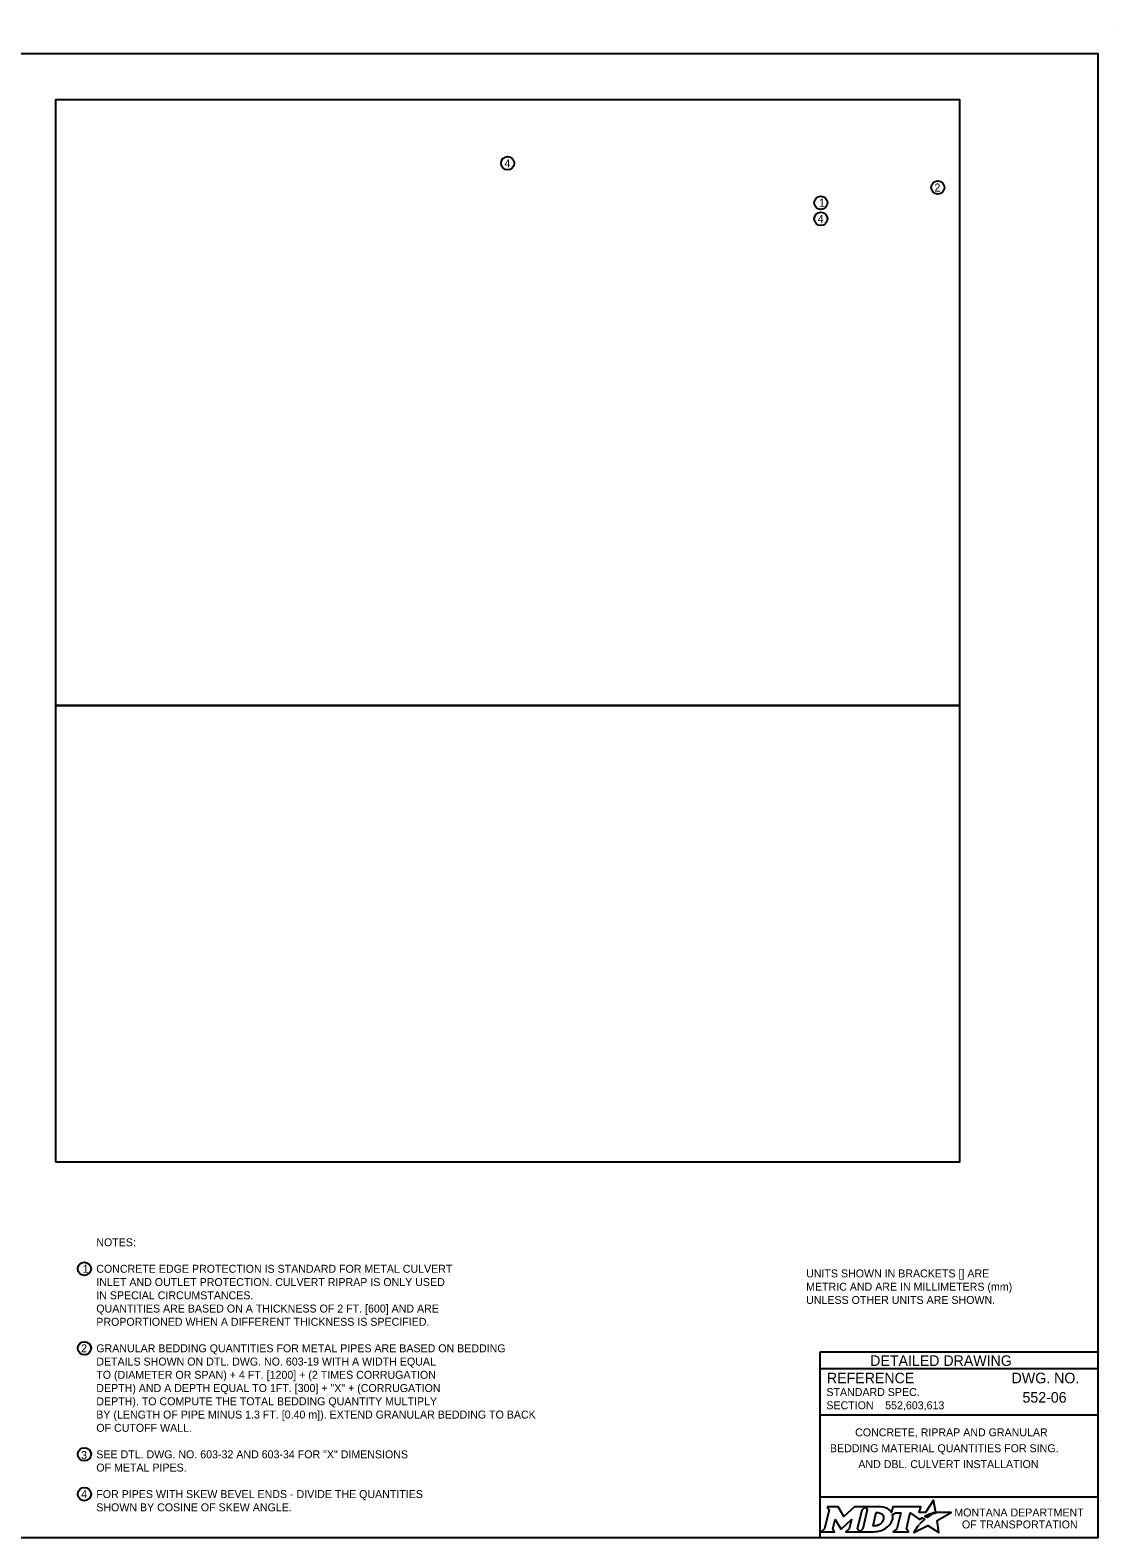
# Model space of a CAD drawing. Extents: x 49991.4 to 50047.6, y 49987.6 to 50011.4.
# Drawn here: x 50008.69 to 50016.9, y 49987.8 to 49999.18 of the extents above; entities that cross this region are included whole.
import ezdxf

# ---------------------------------------------------------------- set-up
doc = ezdxf.new("R2010")
doc.units = 0
for name, color, linetype in [('Default', 7, 'Continuous'), ('Level 1', 7, 'Continuous'), ('Level 2', 7, 'Continuous'), ('Level 5', 7, 'Continuous')]:
    doc.layers.add(name, color=color, linetype=linetype)

msp = doc.modelspace()

# ---------------------------------------------------------------- linework, layer by layer
at = {"layer": 'Default'}
for points in [[(50008.881, 49994.079), (50015.707, 49994.079), (50015.707, 49998.649), (50008.881, 49998.649)], [(50008.881, 49990.635), (50015.707, 49990.635), (50015.707, 49994.079), (50008.881, 49994.079)]]:
    msp.add_lwpolyline(points, close=True, dxfattribs=at)
for points in [[(50015.513, 49987.981), (50015.502, 49987.987), (50015.514, 49987.99), (50015.526, 49987.991), (50015.508, 49988.082), (50015.449, 49987.99), (50015.401, 49987.99), (50015.412, 49988.034), (50015.202, 49988.034), (50015.192, 49987.991), (50015.186, 49988)], [(50014.706, 49988.034), (50014.72, 49988.01), (50014.686, 49987.867), (50014.66, 49987.845), (50014.762, 49987.845), (50014.749, 49987.867), (50014.765, 49987.937), (50014.809, 49987.868), (50014.814, 49987.868), (50014.889, 49987.938), (50014.872, 49987.867), (50014.848, 49987.845), (50014.949, 49987.845), (50014.936, 49987.868), (50014.969, 49988.011)], [(50014.969, 49988.011), (50014.994, 49988.034), (50014.912, 49988.034), (50014.832, 49987.961), (50014.788, 49988.034), (50014.706, 49988.034)], [(50015.108, 49988.034), (50014.994, 49988.034), (50015.009, 49988.011), (50014.975, 49987.867), (50014.949, 49987.845), (50015.06, 49987.845)], [(50015.132, 49987.947), (50015.13, 49987.939), (50015.127, 49987.93), (50015.123, 49987.922), (50015.118, 49987.914), (50015.111, 49987.907), (50015.103, 49987.901), (50015.095, 49987.896), (50015.086, 49987.892), (50015.077, 49987.89), (50015.067, 49987.889), (50015.052, 49987.889), (50015.075, 49987.989), (50015.091, 49987.989), (50015.099, 49987.988), (50015.106, 49987.986), (50015.113, 49987.983), (50015.119, 49987.979), (50015.124, 49987.974), (50015.128, 49987.968), (50015.13, 49987.962), (50015.132, 49987.955), (50015.132, 49987.952), (50015.132, 49987.947)], [(50015.199, 49987.975), (50015.224, 49987.988), (50015.261, 49987.988), (50015.232, 49987.867), (50015.205, 49987.845), (50015.321, 49987.845), (50015.304, 49987.867), (50015.332, 49987.988), (50015.403, 49987.936), (50015.424, 49987.951), (50015.444, 49987.94)], [(50015.388, 49987.884), (50015.373, 49987.86), (50015.368, 49987.852), (50015.362, 49987.844), (50015.36, 49987.839), (50015.465, 49987.893), (50015.549, 49987.838), (50015.536, 49987.93), (50015.643, 49987.989), (50015.594, 49987.989), (50015.564, 49987.99), (50015.543, 49987.99), (50015.536, 49987.989), (50015.531, 49987.987), (50015.523, 49987.985), (50015.513, 49987.981)], [(50015.462, 49987.954), (50015.46, 49987.952), (50015.442, 49987.961), (50015.452, 49987.967), (50015.456, 49987.969), (50015.465, 49987.973), (50015.47, 49987.976), (50015.478, 49987.979), (50015.485, 49987.982), (50015.497, 49987.974), (50015.493, 49987.972), (50015.489, 49987.97), (50015.484, 49987.967), (50015.479, 49987.965), (50015.478, 49987.963), (50015.475, 49987.962), (50015.472, 49987.96), (50015.47, 49987.959), (50015.467, 49987.957), (50015.465, 49987.955), (50015.462, 49987.954)], [(50015.106, 49987.852), (50015.114, 49987.855), (50015.127, 49987.86), (50015.148, 49987.871)], [(50015.402, 49987.9), (50015.402, 49987.9)]]:
    msp.add_lwpolyline(points, dxfattribs=at)
for centre in [(50012.294, 49998.171), (50014.658, 49997.751), (50009.099, 49988.129)]:
    msp.add_circle(centre, 0.05, dxfattribs=at)
for centre, radius, start, end in [((50015.087, 49987.973), 0.118, 300.9103, 339.1383), ((50015.131, 49987.955), 0.0709, 339.5329, 15.8582)]:
    msp.add_arc(centre, radius, start, end, dxfattribs=at)
for centre, major_axis, ratio, start_param, end_param in [((50015.106, 49987.986), (0.0834, -0.0037), 0.568097, 0.61298, 1.570796), ((50015.161, 49987.994), (0.0361, -0.0295), 0.469099, 1.225588, 1.570796), ((50015.433, 49987.93), (-0.0112, -0.0097), 0.021651, 3.157348, 6.283185), ((50015.06, 49987.993), (0, 0.148), 0.987302, 3.139398, 3.456847), ((50015.395, 49987.892), (-0.00694, -0.00806), 0.008222, 0, 3.137361), ((50015.412, 49987.911), (-0.0098, -0.0102), 0.016458, 3.141593, 6.279097)]:
    msp.add_ellipse(centre, major_axis=major_axis, ratio=ratio, start_param=start_param, end_param=end_param, dxfattribs=at)
at = {"layer": 'Level 1'}
msp.add_line((50016.9, 49999.176), (50016.9, 49999.176), dxfattribs=at)
msp.add_lwpolyline([(49999.384, 49998.999), (50016.75, 49998.999), (50016.75, 49987.799), (49999.384, 49987.799)], close=True, dxfattribs=at)
at = {"layer": 'Level 2'}
for centre in [(50015.541, 49997.988), (50014.658, 49997.873), (50009.099, 49989.829), (50009.099, 49989.229), (50009.099, 49988.429)]:
    msp.add_circle(centre, 0.05, dxfattribs=at)
at = {"layer": 'Level 5'}
for p, q in [((50016.75, 49989.199), (50014.65, 49989.199)), ((50014.65, 49989.199), (50014.65, 49987.799)), ((50016.75, 49989.074), (50014.65, 49989.074)), ((50016.386, 49988.859), (50016.386, 49988.859)), ((50016.75, 49988.724), (50014.65, 49988.724)), ((50015.144, 49988.799), (50015.144, 49988.799)), ((50015.7, 49988.475), (50015.7, 49988.475)), ((50016.75, 49988.106), (50014.65, 49988.106))]:
    msp.add_line(p, q, dxfattribs=at)

# ---------------------------------------------------------------- texts
at = {"layer": 'Default'}
for s, p in [('4', (50012.27, 49998.141)), ('4', (50014.634, 49997.721)), ('4', (50009.075, 49988.099)), ('MONTANA DEPARTMENT', (50015.666, 49987.96)), ('OF TRANSPORTATION', (50015.723, 49987.87))]:
    msp.add_text(s, height=0.06, dxfattribs=at).set_placement(p)
at = {"layer": 'Level 2'}
for s, height, p in [('2', 0.06, (50015.516, 49997.958)), ('1', 0.06, (50014.644, 49997.843)), ('NOTES:', 0.06, (50009.189, 49989.999)), ('1', 0.06, (50009.086, 49989.799)), ('CONCRETE EDGE PROTECTION IS STANDARD FOR METAL CULVERT', 0.06, (50009.189, 49989.799)), ('INLET AND OUTLET PROTECTION. CULVERT RIPRAP IS ONLY USED ', 0.06, (50009.189, 49989.699)), ('UNITS SHOWN IN BRACKETS [] ARE ', 0.06, (50014.547, 49989.764)), ('IN SPECIAL CIRCUMSTANCES. ', 0.06, (50009.189, 49989.599)), ('METRIC AND ARE IN MILLIMETERS (mm) ', 0.06, (50014.547, 49989.664)), ('QUANTITIES ARE BASED ON A THICKNESS OF 2 FT. [600] AND ARE', 0.06, (50009.189, 49989.499)), ('UNLESS OTHER UNITS ARE SHOWN.', 0.06, (50014.547, 49989.564)), ('PROPORTIONED WHEN A DIFFERENT THICKNESS IS SPECIFIED.', 0.06, (50009.189, 49989.399)), ('2', 0.06, (50009.074, 49989.199)), ('GRANULAR BEDDING QUANTITIES FOR METAL PIPES ARE BASED ON BEDDING', 0.06, (50009.189, 49989.199)), ('DETAILS SHOWN ON DTL. DWG. NO. 603-19 WITH A WIDTH EQUAL ', 0.06, (50009.189, 49989.099)), ('TO (DIAMETER OR SPAN) + 4 FT. [1200] + (2 TIMES CORRUGATION ', 0.06, (50009.189, 49988.999)), ('DEPTH) AND A DEPTH EQUAL TO 1FT. [300] + "X" + (CORRUGATION ', 0.06, (50009.189, 49988.899)), ('DEPTH). TO COMPUTE THE TOTAL BEDDING QUANTITY MULTIPLY ', 0.06, (50009.189, 49988.799)), ('552-06', 0.08, (50016.18, 49988.819)), ('BY (LENGTH OF PIPE MINUS 1.3 FT. [0.40 m]). EXTEND GRANULAR BEDDING TO BACK', 0.06, (50009.189, 49988.699)), ('552,603,613', 0.06, (50015.144, 49988.769)), ('OF CUTOFF WALL. ', 0.06, (50009.189, 49988.599)), ('CONCRETE, RIPRAP AND GRANULAR', 0.06, (50014.917, 49988.565)), ('BEDDING MATERIAL QUANTITIES FOR SING.', 0.06, (50014.727, 49988.445)), ('3', 0.06, (50009.074, 49988.393)), ('SEE DTL. DWG. NO. 603-32 AND 603-34 FOR "X" DIMENSIONS', 0.06, (50009.189, 49988.399)), ('AND DBL. CULVERT INSTALLATION', 0.06, (50014.941, 49988.325)), ('OF METAL PIPES.', 0.06, (50009.189, 49988.299)), ('FOR PIPES WITH SKEW BEVEL ENDS - DIVIDE THE QUANTITIES', 0.06, (50009.189, 49988.099)), ('SHOWN BY COSINE OF SKEW ANGLE.', 0.06, (50009.189, 49987.999))]:
    msp.add_text(s, height=height, dxfattribs=at).set_placement(p)
at = {"layer": 'Level 5'}
for s, height, p in [('DETAILED DRAWING', 0.0799, (50015.031, 49989.096)), ('REFERENCE', 0.08, (50014.704, 49988.965)), ('DWG. NO.', 0.08, (50016.098, 49988.965)), ('STANDARD SPEC.', 0.06, (50014.7, 49988.869)), ('SECTION', 0.06, (50014.7, 49988.769))]:
    msp.add_text(s, height=height, dxfattribs=at).set_placement(p)

doc.saveas('drawing.dxf')
